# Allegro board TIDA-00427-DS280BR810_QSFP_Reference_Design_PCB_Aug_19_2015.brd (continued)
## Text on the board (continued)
BOTTOM: DS280BR810_QSFP_0609_PCB ARTWORK BOTTOM
Ref Des/Assembly Bottom: DS280BR810_QSFP_0609_PCB BOTTOM-ASSY
Ref Des/Silkscreen Bottom: ID2 | ID1 | ID3
User.Comments: 1 | 15 | A | J | EDGE OF BOARD | 3 | 4 | 14 | 2 | 13 | HOST | CABLE | 5
TOP: DS280BR810_QSFP_0609_PCB ARTWORK TOP
Ref Des/Assembly Top: DS280BR810_QSFP_0609_PCB TOP-ASSY | Press fit
Ref Des/Silkscreen Top: ID5 | ID4 | ID6 | 3V3 | SV601171- | DS2x0x810_QSFP28_EVM | Rev A | GND | 2V5 | HOST | CABLE
ART02: DS280BR810_QSFP_0609_PCB ARTWORK LAYER02
GND03: DS280BR810_QSFP_0609_PCB GROUND PLANE03
ART04: DS280BR810_QSFP_0609_PCB ARTWORK LAYER04
GND05: DS280BR810_QSFP_0609_PCB GROUND PLANE05
POWER06: DS280BR810_QSFP_0609_PCB POWER PLANE06
POWER07: DS280BR810_QSFP_0609_PCB POWER PLANE07
GND08: DS280BR810_QSFP_0609_PCB GROUND PLANE08
ART09: DS280BR810_QSFP_0609_PCB ARTWORK LAYER09
GND10: DS280BR810_QSFP_0609_PCB GROUND PLANE10
ART11: DS280BR810_QSFP_0609_PCB ARTWORK LAYER11
DIMENSION: For Flash D-Code | 50:Recommended Thermal pad's OD(out-diamter)is 50mil | 0:It means as angle,but we can ignore it here,The priority Thermal angle is 45 | (Thermal pad's angle,W,ID depends on the ability of the factory,they'll adjusted the paramete) | For example :  FLASH 50 0 D33 | FLASH:The D code shape is THERMAL | D33:Flaged the D code | Note:If OD not bigger than D,then The D code will full connected this hole. | (Some of the via used this method) | W | ID | OD | D | 45 | Rogers4350 | RO4450B | FR-4 | Prepreg    4 MIl | Core 8 MIl | Prepreg 4 MIl | Core12.2Mil | 1 OZ   Layer1 | 0.5 OZ   Layer2 | 0.5 OZ   Layer3 | 0.5 OZ   Layer4 | 0.5 OZ   Layer5 | 0.5 OZ   Layer6 | 0.5 OZ   Layer7 | 0.5 OZ   Layer8 | 0.5 OZ   Layer9 | 0.5 OZ   Layer10 | 0.5 OZ   Layer11 | 1 OZ   Layer12 | DS280BR810_QSFP_0609_PCB DRILL | MAX45 | 30 | T | 1/3T | MIN0.30mm MAX0.70mm | Dielectric Material: | Tg: | BOARD NAME: | BOARD THICKNESS: | SOLDER COLORS: | SILKSCREEN COLORS: | CONTROL IMPEDANCE: YES | SPELL MODE: 1 : 1 | OUTLINE PROFILE:ROUTER     BRIDGE   STAMP HOLE   V-CUT(ANGLE 30) | INSPECTION STANDARD:IPC-II      IPC-III      GB-4588      OTHER | VIA TECHNIC:ALL VIA FILLED           BY GERBER | PRESSFIT HOLES:                      YES(TOLERANCE+/-0.05mm) | BOW AND TWIST TOLERANCE:<=0.75%            Specify   % | DESIGN BY: | OTHER: | 1.OBLONG VIAS: | 2.Drill tolerance+/-1.95mil[+/-0.05mm] for | DS2x0x810_QSFP28_EVM | 2 | MM +/-10% | Golden Finger,Others HASL(Pb-Free) | Golden Finger,Others HASL(Sn/Pb) | FR-4+R4350 | Other | BOARD LAYERS: | SOLDER MASK: IPC SM-840 | Pb LOGO: YES | OPEN WINDOWS:  NO | V-cut Detail: | 12 | Golden Finger,Others ENIG | Golden Finger,Others OSP | LAYER | L1 | L2 | L4 | L9 | L11 | L12 | SURFACE FINISHED: | IMPEDANCE | 50 OHM | Common Tg\S1141 | SINGLE IMPEDANCE (+/- 5)% | WIDTH | 7.2MIL | 5.2MIL | OSP | GREEN | WHITE | S1000H | HASL(Sn/Pb) | REF LAYER | RED | ImAg | S1000-2M\IT180A | Impedance Control Table | HASL(Pb-Free) | 100 OHM | ImSn | YELLOW | OTHER\S1150G | 6.3 Mil | 4.3 Mil | IMMERSION GOLD | DIFF IMPEDANCE (+/- 5%) | OTHER | SPACE | 9.7MIL | 5.9mil | OTHER\S1165 | 3. ANY CHANGES MADE BY THE PCB FABRICATOR TO THE FILM OR | 4. DEBURR ALL SHARP EDGES. | 5. THIS BOARD IS ROHS COMPLAINT AND LEAD FREE. | 2.REMOVE THE NON-FUNCTIONAL PADS ON ALL INNER LAYERS. | 1.NO VENDOR LOGO OR NAME ON THE BOARD. | NOTES (UNLESS OTHERWISE SPECIFIED): | THE GERBER FILES MUST BE APPROVED BY TI. | Revision: | Rev A | Data: | 2015-06-09 | Designer: | QA: | DS280BR810_QSFP_0609_PCB DRILL CHART | 1--Gerber TOP | 2--Gerber LAYER02 | 3--GROUND PLANE03 | 4--Gerber LAYER04 | 5--GROUND PLANE05 | 6--POWER PLANE06 | 7--POWER PLANE07 | 8--GROUND PLANE08 | 9--Gerber LAYER09 | 10--GROUND PLANE10 | 11--Gerber LAYER11 | 12--Gerber BOTTOM | Texas Instruments Incorporated | 207.87(MM) | 8184.00(Mils) | 3879.00(Mils) | 98.53(MM)
DISPLAY_BOTTOM: DS280BR810_QSFP_0609_PCB PASTEMASK BOTTOM
DISPLAY_TOP: DS280BR810_QSFP_0609_PCB PASTEMASK TOP
COMPVAL_TYPE_BOTTOM: FIGURE | SIZE | 8.0 | 10.0 | 14.57 | 22.05 | 40.0 | 41.34 | 98.43 | 130.0 | 255.0 | 35.43 | DRILL CHART: TOP to BOTTOM | ALL UNITS ARE IN MILS | TOLERANCE | PLATED | NON-PLATED | QTY | 174 | 474 | 152 | 6 | 137 | 20 | 4 | 3 | 2
DEVICE_TYPE_BOTTOM: NOTES: | - DRILL SIZES LISTED IN LEGEND | ARE CONSIDERED FINISHED. | - VENDOR IS REQUIRED TO SELECT | TOOLING FOR OVERDRILLING. | - STUB LENGTH SHOULD BE LESS THAN | 8MIL.
User.8: FIGURE | SIZE | 8.0 | 14.57 | BACKDRILL: BOTTOM to GND10 | ALL UNITS ARE IN MILS | TOLERANCE | +0.0/-0.0 | +2.0/-2.0 | PLATED | QTY | 32
User.11: NAME: TIDA00427_DS280BR810_QSFP_Reference_Design | DATE: June 2015 | LAYER | LAYER: | JOB: | SV601171 | REV:A
User.12: DS280BR810_QSFP_0609_PCB ADT
User.13: DS280BR810_QSFP_0609_PCB ADB
User.14: DS280BR810_QSFP_0609_PCB ALL
User.15: DS280BR810_QSFP_0609_PCB SILKTOP
User.16: DS280BR810_QSFP_0609_PCB SILKBOTM
User.17: DS280BR810_QSFP_0609_PCB XSILK2SOLD_TOP
User.18: DS280BR810_QSFP_0609_PCB XSILK2SOLD_BOTM
User.19: DS280BR810_QSFP_0609_PCB SOLDTOP
User.20: DS280BR810_QSFP_0609_PCB SOLDBOTM
User.21: DS280BR810_QSFP_0609_PCB OUTLINE
